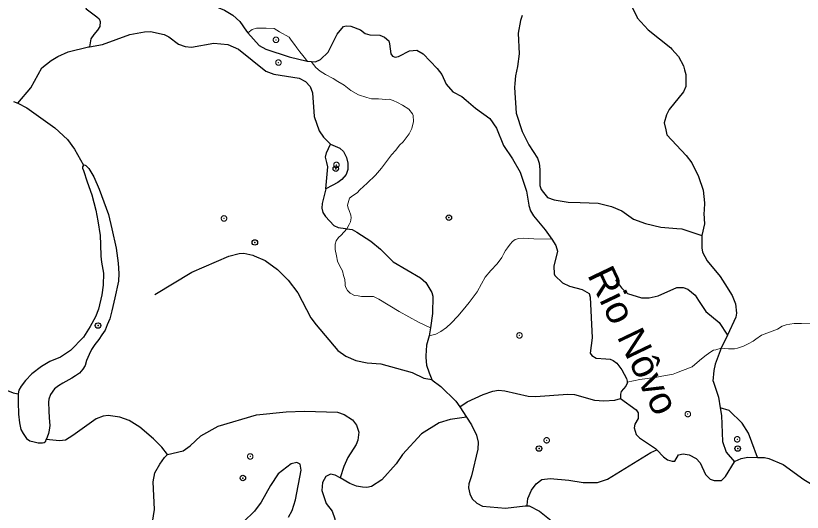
# Model space of a CAD drawing. Extents: x 267.7 to 296, y 7537.7 to 7565.8.
# Drawn here: x 270.298 to 273.164, y 7556.895 to 7558.704 of the extents above; entities that cross this region are included whole.
import ezdxf
from ezdxf.enums import TextEntityAlignment as Align

# ---------------------------------------------------------------- set-up
doc = ezdxf.new("R2010")
doc.units = 0
doc.header["$LTSCALE"] = 0.04
doc.header["$PDMODE"] = 32
doc.header["$PDSIZE"] = 0.02
doc.linetypes.add('SHORT_DASHED', pattern=[2.7, 1.5, -1.2])
for name, color, linetype, lineweight in [('2', 7, 'Continuous', 25), ('21', 7, 'SHORT_DASHED', 13), ('7', 7, 'Continuous', 25)]:
    doc.layers.add(name, color=color, linetype=linetype, lineweight=lineweight)
doc.layers.add('54', color=7, linetype='Continuous')
doc.layers.add('61', color=7, linetype='Continuous')

msp = doc.modelspace()

# ---------------------------------------------------------------- linework, layer by layer
at = {"layer": '2'}
for points in [[(270.5446, 7558.1593), (270.5418, 7558.1539), (270.5411, 7558.1483), (270.5446, 7558.1405), (270.5587, 7558.0989), (270.5756, 7558.0517), (270.5904, 7557.9961), (270.5974, 7557.9566), (270.6059, 7557.9031), (270.6066, 7557.8699), (270.608, 7557.8277), (270.6108, 7557.8058), (270.6179, 7557.7657), (270.6172, 7557.7227), (270.6122, 7557.6867), (270.5995, 7557.6346), (270.589, 7557.6071), (270.5692, 7557.5719), (270.5453, 7557.5331), (270.4974, 7557.4838), (270.4614, 7557.4605), (270.4227, 7557.4443), (270.3924, 7557.426), (270.3572, 7557.3999), (270.3332, 7557.3746), (270.3184, 7557.3541), (270.3099, 7557.3401), (270.3064, 7557.326)], [(270.5446, 7558.1593), (270.5486, 7558.1601), (270.5535, 7558.1587), (270.5645, 7558.1467), (270.5824, 7558.1164), (270.6022, 7558.0717), (270.6365, 7557.9803), (270.648, 7557.9276), (270.6639, 7557.857), (270.6708, 7557.8024), (270.6738, 7557.7651), (270.6723, 7557.7368), (270.6594, 7557.6762), (270.648, 7557.6285), (270.641, 7557.5997), (270.6311, 7557.5773), (270.6241, 7557.5589), (270.6117, 7557.541), (270.6003, 7557.5246), (270.5858, 7557.5067), (270.5744, 7557.4874), (270.5655, 7557.4695), (270.5565, 7557.4481), (270.5511, 7557.4297), (270.5431, 7557.4168), (270.5302, 7557.4019), (270.5163, 7557.3915), (270.5019, 7557.3835), (270.4701, 7557.3651), (270.4537, 7557.3552), (270.4398, 7557.3443), (270.4248, 7557.3244), (270.4189, 7557.307), (270.4179, 7557.2956), (270.4184, 7557.2647), (270.4199, 7557.2394), (270.4219, 7557.2116), (270.4199, 7557.1937), (270.4169, 7557.1823), (270.4129, 7557.1684), (270.4092, 7557.1604)], [(270.3064, 7557.326), (270.3064, 7557.2964), (270.3078, 7557.2527), (270.3114, 7557.221), (270.317, 7557.1963), (270.3247, 7557.1815), (270.3367, 7557.1639), (270.3494, 7557.1554), (270.3649, 7557.1512), (270.3797, 7557.1477), (270.3959, 7557.1477), (270.4022, 7557.1498), (270.4072, 7557.154), (270.4092, 7557.1604)]]:
    msp.add_lwpolyline(points, dxfattribs=at)
msp.add_point((270.598, 7557.5751), dxfattribs=at)
at = {"layer": '21'}
for points in [[(271.1436, 7558.6417), (271.1597, 7558.6537), (271.1749, 7558.6582), (271.2105, 7558.659), (271.2393, 7558.6567), (271.2597, 7558.6446), (271.2945, 7558.6257), (271.3021, 7558.6151), (271.3135, 7558.5984), (271.3218, 7558.587), (271.3331, 7558.5719), (271.3445, 7558.559), (271.3543, 7558.5469), (271.3596, 7558.5385)], [(271.3749, 7558.5371), (271.3914, 7558.5151), (271.4073, 7558.5022), (271.427, 7558.4894), (271.4551, 7558.4757), (271.4717, 7558.4644), (271.4944, 7558.4507), (271.5194, 7558.4311), (271.5467, 7558.4152), (271.5777, 7558.4061), (271.5951, 7558.4015), (271.6194, 7558.4008), (271.6466, 7558.3985), (271.6587, 7558.3993), (271.6731, 7558.3947), (271.6898, 7558.3879), (271.7072, 7558.3781), (271.7307, 7558.3629), (271.7443, 7558.347), (271.7466, 7558.3402), (271.7473, 7558.319), (271.742, 7558.2925), (271.7322, 7558.2736), (271.7095, 7558.244), (271.6966, 7558.2319), (271.6837, 7558.2145), (271.6671, 7558.1971), (271.6527, 7558.1774), (271.6315, 7558.1486), (271.6088, 7558.1236), (271.5785, 7558.0934), (271.552, 7558.0691), (271.5421, 7558.0585), (271.5255, 7558.0479), (271.5141, 7558.0388), (271.5073, 7558.0139), (271.5096, 7558.0033), (271.5126, 7557.9942), (271.5194, 7557.9775), (271.5202, 7557.9677), (271.5179, 7557.9533), (271.5134, 7557.9427), (271.5042, 7557.928)], [(271.5042, 7557.928), (271.4838, 7557.9048), (271.474, 7557.8957), (271.4657, 7557.8836), (271.4626, 7557.8715), (271.4626, 7557.8518), (271.4672, 7557.8291), (271.471, 7557.8102), (271.4793, 7557.7912), (271.4884, 7557.7746), (271.4929, 7557.7579), (271.4975, 7557.7428), (271.499, 7557.7276), (271.499, 7557.7216), (271.5005, 7557.7133), (271.5065, 7557.7026), (271.5171, 7557.6936), (271.533, 7557.6852), (271.5459, 7557.683), (271.558, 7557.6814), (271.5785, 7557.6814), (271.5906, 7557.6814), (271.6012, 7557.6807), (271.6209, 7557.6716), (271.6951, 7557.6269), (271.7663, 7557.5876), (271.809, 7557.5667)], [(271.8045, 7557.5381), (271.8291, 7557.5444), (271.8473, 7557.5535), (271.8677, 7557.5686), (271.8851, 7557.5845), (271.9094, 7557.6088), (271.9283, 7557.6322), (271.9502, 7557.6595), (271.979, 7557.6981), (271.9957, 7557.7276), (272.0093, 7557.7511), (272.0298, 7557.7761), (272.0525, 7557.8003), (272.0691, 7557.823), (272.0767, 7557.8382), (272.0828, 7557.8488), (272.0896, 7557.8586), (272.0994, 7557.8715), (272.1085, 7557.8813), (272.1183, 7557.8889), (272.1312, 7557.8927), (272.1501, 7557.8935), (272.1865, 7557.8912), (272.2513, 7557.8895)], [(272.8686, 7557.4924), (272.895, 7557.4901), (272.917, 7557.4901), (272.9277, 7557.4929), (272.9502, 7557.5002), (272.9677, 7557.5087), (272.9858, 7557.5189), (272.9948, 7557.5262), (273.0157, 7557.5397), (273.0444, 7557.551), (273.0738, 7557.5617), (273.0913, 7557.573), (273.1059, 7557.5781), (273.1195, 7557.5803), (273.1347, 7557.5826), (273.1612, 7557.5826), (273.1939, 7557.5837)], [(272.5261, 7557.3688), (272.5718, 7557.379), (272.6338, 7557.3869), (272.6519, 7557.3914), (272.6936, 7557.3987), (272.706, 7557.4032), (272.728, 7557.4111), (272.763, 7557.4252), (272.79, 7557.4478), (272.8092, 7557.4636), (272.8278, 7557.4771), (272.8402, 7557.485), (272.8493, 7557.4867), (272.8686, 7557.4924)]]:
    msp.add_lwpolyline(points, dxfattribs=at)
for p in [(271.2463, 7558.6159), (271.2554, 7558.5332), (271.4667, 7558.1603), (271.057, 7557.9655), (272.1336, 7557.5393), (272.7472, 7557.2527), (272.2328, 7557.1572), (272.9272, 7557.1609), (271.1526, 7557.0984)]:
    msp.add_point(p, dxfattribs=at)
at = {"layer": '54'}
for p in [(271.4643, 7558.1465), (271.8765, 7557.9684), (271.1694, 7557.8779), (272.205, 7557.1272), (272.9289, 7557.1272), (271.1258, 7557.0199)]:
    msp.add_point(p, dxfattribs=at)
at = {"layer": '7'}
for p, q in [((270.2902, 7558.3919), (270.3059, 7558.3849)), ((272.8912, 7557.5397), (272.8686, 7557.4924)), ((271.916, 7557.2788), (271.9408, 7557.2409))]:
    msp.add_line(p, q, dxfattribs=at)
for points in [[(270.7124, 7558.7626), (270.7121, 7558.7621), (270.6936, 7558.7622), (270.6228, 7558.7724), (270.5976, 7558.7709), (270.5785, 7558.7623), (270.561, 7558.751), (270.5528, 7558.7367), (270.5547, 7558.7287), (270.594, 7558.6998), (270.6021, 7558.6925), (270.6062, 7558.6832), (270.6051, 7558.6647), (270.5959, 7558.6514), (270.5826, 7558.635), (270.5723, 7558.6196), (270.5666, 7558.591)], [(270.9731, 7558.7578), (270.9969, 7558.7495), (271.0592, 7558.7238), (271.0887, 7558.7053), (271.1145, 7558.6832), (271.1386, 7558.6474), (271.1436, 7558.6417)], [(272.543, 7558.7366), (272.5623, 7558.698), (272.563, 7558.6967), (272.6032, 7558.6519), (272.6849, 7558.5868), (272.6887, 7558.5825), (272.7127, 7558.5549), (272.7309, 7558.5216), (272.735, 7558.5064), (272.7397, 7558.4891), (272.7403, 7558.4463), (272.7313, 7558.427), (272.6797, 7558.3617), (272.67, 7558.343), (272.661, 7558.3137), (272.6666, 7558.2885), (272.6707, 7558.2697), (272.7412, 7558.1952), (272.7618, 7558.1676), (272.786, 7558.1182), (272.8027, 7558.0684), (272.8083, 7558.0228), (272.8066, 7557.995), (272.8059, 7557.9833), (272.8083, 7557.9453), (272.7979, 7557.9033)], [(272.143, 7558.7051), (272.137, 7558.6865), (272.1293, 7558.6404), (272.1324, 7558.5644), (272.1267, 7558.5193), (272.1187, 7558.4853), (272.1167, 7558.4573), (272.1156, 7558.4426), (272.1213, 7558.3494), (272.1435, 7558.2825), (272.1679, 7558.2338), (272.1994, 7558.1849), (272.2056, 7558.1664), (272.2083, 7558.1442), (272.2079, 7558.0858), (272.2127, 7558.0707), (272.2214, 7558.0598), (272.2358, 7558.0418), (272.2602, 7558.033), (272.3106, 7558.0249), (272.3544, 7558.0232), (272.421, 7558.0206), (272.4688, 7558.0094), (272.5071, 7557.9936), (272.5491, 7557.9629), (272.5925, 7557.9469), (272.6491, 7557.9333), (272.7074, 7557.9285), (272.7249, 7557.9271), (272.7979, 7557.9033)], [(271.3749, 7558.5371), (271.3903, 7558.5358), (271.4092, 7558.5446), (271.4363, 7558.5713), (271.4699, 7558.6362), (271.4922, 7558.6641), (271.5021, 7558.6668), (271.5193, 7558.666), (271.5544, 7558.6519), (271.5719, 7558.6392), (271.5883, 7558.6338), (271.6246, 7558.6333), (271.6422, 7558.6262), (271.6578, 7558.6118), (271.6603, 7558.6011), (271.6651, 7558.5646), (271.6716, 7558.557), (271.6808, 7558.5529), (271.6931, 7558.5549), (271.6954, 7558.5562), (271.7331, 7558.5765), (271.76, 7558.5781), (271.7822, 7558.5644), (271.8335, 7558.5117), (271.8509, 7558.4894), (271.867, 7558.4543), (271.8904, 7558.427), (271.9233, 7558.4099), (271.9399, 7558.3956), (271.973, 7558.3671), (272.0258, 7558.329), (272.0502, 7558.2937), (272.0756, 7558.2316), (272.1086, 7558.183), (272.1366, 7558.1335), (272.1593, 7558.0645), (272.1677, 7558.0143), (272.168, 7558.0124), (272.1741, 7557.9931), (272.1845, 7557.9746), (272.2279, 7557.9242), (272.2513, 7557.8895)], [(270.5666, 7558.591), (270.6145, 7558.5988), (270.7136, 7558.6355), (270.7671, 7558.6451), (270.7895, 7558.6458), (270.8386, 7558.6349), (270.8557, 7558.6264), (270.8915, 7558.5996), (270.9151, 7558.5919), (270.9388, 7558.5892), (271.0197, 7558.604), (271.0708, 7558.5989), (271.1095, 7558.5824), (271.2096, 7558.5021), (271.2384, 7558.4903), (271.3308, 7558.4768), (271.3536, 7558.4644), (271.3708, 7558.4465), (271.3793, 7558.4233), (271.386, 7558.3369), (271.4036, 7558.2848), (271.4201, 7558.2614), (271.4445, 7558.2364)], [(271.1436, 7558.6417), (271.1847, 7558.5949), (271.2095, 7558.5815), (271.2939, 7558.5539), (271.3596, 7558.5385)], [(270.3059, 7558.3849), (270.3532, 7558.4408), (270.3928, 7558.5137), (270.4269, 7558.5403), (270.452, 7558.5554), (270.489, 7558.572), (270.5634, 7558.5905), (270.5666, 7558.591)], [(271.3596, 7558.5385), (271.3629, 7558.5382), (271.3749, 7558.5371)], [(270.3059, 7558.3849), (270.3062, 7558.3848), (270.3391, 7558.3688), (270.4406, 7558.295), (270.4862, 7558.2528), (270.5118, 7558.2176), (270.5446, 7558.1593)], [(271.4279, 7558.0729), (271.4348, 7558.1529), (271.4313, 7558.1689), (271.427, 7558.1885), (271.4303, 7558.2046), (271.4445, 7558.2364)], [(271.4445, 7558.2364), (271.4446, 7558.2363), (271.479, 7558.2213), (271.4796, 7558.2208), (271.493, 7558.209), (271.5033, 7558.1875), (271.5084, 7558.1669), (271.5084, 7558.1433), (271.5022, 7558.1249), (271.4868, 7558.1074), (271.4714, 7558.0961), (271.4509, 7558.0848), (271.4279, 7558.0729)], [(271.4279, 7558.0729), (271.4143, 7558.0202), (271.4131, 7558.0025), (271.4177, 7557.9872), (271.4263, 7557.9729), (271.4571, 7557.9401), (271.4725, 7557.9329), (271.4992, 7557.9288), (271.5042, 7557.928)], [(271.5042, 7557.928), (271.5238, 7557.9247), (271.5412, 7557.9155), (271.5921, 7557.8821), (271.6279, 7557.8532), (271.6735, 7557.8078), (271.7728, 7557.749), (271.7923, 7557.7319), (271.8147, 7557.696), (271.818, 7557.6822), (271.8173, 7557.6187), (271.809, 7557.5667), (271.8045, 7557.5381)], [(272.2513, 7557.8895), (272.2667, 7557.8665), (272.2719, 7557.8459), (272.2593, 7557.7913), (272.2596, 7557.764), (272.2625, 7557.7577), (272.2902, 7557.7309), (272.3156, 7557.7182), (272.3624, 7557.7067), (272.3872, 7557.6917), (272.3917, 7557.679), (272.3989, 7557.531), (272.3909, 7557.4743), (272.3968, 7557.4657), (272.4135, 7557.4568), (272.4487, 7557.454), (272.4647, 7557.4527), (272.4753, 7557.4478), (272.4885, 7557.4379), (272.5073, 7557.4134), (272.524, 7557.3825), (272.5261, 7557.3728), (272.5261, 7557.3688)], [(272.7979, 7557.9033), (272.798, 7557.8583), (272.8012, 7557.843), (272.818, 7557.8109), (272.8653, 7557.7538), (272.8818, 7557.7274), (272.9082, 7557.6851), (272.9207, 7557.6544), (272.9247, 7557.62), (272.9224, 7557.6052), (272.8912, 7557.5397)], [(270.8046, 7557.6883), (270.9398, 7557.7698), (271.0748, 7557.8275), (271.1128, 7557.8381), (271.1293, 7557.8384), (271.1615, 7557.8313), (271.1665, 7557.8291), (271.2066, 7557.8118), (271.2518, 7557.779), (271.2914, 7557.7407), (271.3262, 7557.6946), (271.3735, 7557.6039), (271.3925, 7557.5776), (271.4718, 7557.4847), (271.5011, 7557.4636), (271.5376, 7557.4482), (271.5786, 7557.4396), (271.6282, 7557.4353), (271.7427, 7557.4039), (271.7851, 7557.3838), (271.7925, 7557.3823), (271.8139, 7557.3781)], [(272.484, 7557.7423), (272.506, 7557.7126), (272.5272, 7557.6915), (272.5781, 7557.6766), (272.6064, 7557.6766), (272.6396, 7557.6837), (272.7073, 7557.7142), (272.7301, 7557.7143), (272.7468, 7557.7077), (272.7745, 7557.6863), (272.7867, 7557.667), (272.8126, 7557.6262), (272.8612, 7557.5861), (272.8912, 7557.5397)], [(271.8045, 7557.5381), (271.795, 7557.5037), (271.7924, 7557.4651), (271.792, 7557.4586), (271.7952, 7557.4304), (271.8049, 7557.4033), (271.8139, 7557.3781)], [(272.8686, 7557.4924), (272.8472, 7557.4347), (272.8418, 7557.4118), (272.8389, 7557.373), (272.8391, 7557.3725), (272.8591, 7557.3139), (272.8656, 7557.276)], [(271.8139, 7557.3781), (271.814, 7557.3779), (271.8476, 7557.3533), (271.902, 7557.3002), (271.916, 7557.2788)], [(272.5261, 7557.3688), (272.5261, 7557.3649), (272.5217, 7557.3546), (272.5046, 7557.335), (272.5013, 7557.3258), (272.5017, 7557.3097), (272.5023, 7557.3093)], [(269.9297, 7557.2438), (269.9349, 7557.2729), (269.9482, 7557.3017), (269.9595, 7557.3143), (269.9813, 7557.3317), (270.0585, 7557.3505), (270.1206, 7557.3613), (270.1825, 7557.3649), (270.2038, 7557.3622), (270.2476, 7557.347), (270.2888, 7557.3302), (270.3064, 7557.326)], [(271.916, 7557.2788), (271.9431, 7557.297), (272.0018, 7557.3242), (272.0361, 7557.336), (272.0571, 7557.3398), (272.0804, 7557.3379), (272.165, 7557.3175), (272.1925, 7557.3165), (272.3099, 7557.3249), (272.3338, 7557.324), (272.4074, 7557.3035), (272.4416, 7557.3005), (272.4815, 7557.304), (272.5023, 7557.3093)], [(272.5023, 7557.3093), (272.5591, 7557.2682), (272.5659, 7557.2575), (272.5665, 7557.237), (272.5536, 7557.216), (272.5516, 7557.2029), (272.5586, 7557.1787), (272.5707, 7557.1659), (272.63, 7557.1272), (272.6348, 7557.1221)], [(270.8517, 7557.1049), (270.9082, 7557.1188), (270.9332, 7557.1372), (270.9724, 7557.1737), (271.0358, 7557.2092), (271.1755, 7557.2506), (271.2831, 7557.2607), (271.3504, 7557.2633), (271.4705, 7557.2593), (271.4951, 7557.2516), (271.5256, 7557.2322), (271.5397, 7557.2127), (271.548, 7557.1867), (271.5446, 7557.1582), (271.539, 7557.142), (271.5086, 7557.094), (271.4936, 7557.0613), (271.4807, 7557.0202)], [(273.0017, 7557.0948), (272.9804, 7557.1507), (272.968, 7557.1834), (272.9451, 7557.2201), (272.8975, 7557.266), (272.8656, 7557.276)], [(272.8656, 7557.276), (272.8705, 7557.2474), (272.8731, 7557.1534), (272.887, 7557.1139), (272.9175, 7557.0789)], [(270.8517, 7557.1049), (270.831, 7557.1323), (270.8006, 7557.1631), (270.7497, 7557.2056), (270.711, 7557.2293), (270.6772, 7557.2421), (270.6344, 7557.2478), (270.6165, 7557.2457), (270.5907, 7557.2354), (270.5065, 7557.1744), (270.4796, 7557.1582), (270.4573, 7557.1552), (270.4092, 7557.1604)], [(271.9408, 7557.2409), (271.8808, 7557.2327), (271.8414, 7557.2209), (271.7772, 7557.1805), (271.7073, 7557.105), (271.6839, 7557.0715), (271.6319, 7557.0132), (271.5948, 7556.9884), (271.5769, 7556.9847), (271.5617, 7556.9871), (271.5393, 7556.9906), (271.5153, 7557.0003), (271.4807, 7557.0202)], [(271.9408, 7557.2409), (271.9589, 7557.2133), (271.9769, 7557.1755), (271.9831, 7557.1505), (271.9824, 7557.1252), (271.9594, 7557.0273), (271.9495, 7556.9989), (271.9484, 7556.9842), (271.9531, 7556.9626), (271.9612, 7556.944), (271.9784, 7556.9282), (271.999, 7556.9169), (272.0828, 7556.9096), (272.154, 7556.9187), (272.1619, 7556.9184)], [(272.1619, 7556.9184), (272.1621, 7556.9205), (272.1642, 7556.9458), (272.1781, 7556.9755), (272.1941, 7556.999), (272.2155, 7557.0146), (272.246, 7557.018), (272.314, 7557.0121), (272.3655, 7557.0034), (272.4175, 7557.0035), (272.4543, 7557.0151), (272.6122, 7557.1126), (272.6348, 7557.1221)], [(272.6348, 7557.1221), (272.6582, 7557.0968), (272.6737, 7557.0861), (272.6901, 7557.0809), (272.6999, 7557.0817), (272.7138, 7557.1043), (272.7304, 7557.1085), (272.7515, 7557.1038), (272.7772, 7557.0906), (272.7926, 7557.0756), (272.8113, 7557.0332), (272.8286, 7557.0157), (272.8435, 7557.0102), (272.8702, 7557.011), (272.885, 7557.0252), (272.9175, 7557.0789)], [(270.787, 7556.7966), (270.8041, 7556.9056), (270.7985, 7557.0065), (270.8049, 7557.0383), (270.8235, 7557.0706), (270.8402, 7557.0943), (270.8517, 7557.1049)], [(272.9175, 7557.0789), (272.9193, 7557.0818), (272.9415, 7557.0909), (272.9664, 7557.0953), (273.0017, 7557.0948)], [(273.0017, 7557.0948), (273.0264, 7557.0945), (273.0429, 7557.0913), (273.0948, 7557.0693), (273.1699, 7557.0147), (273.2406, 7556.9724), (273.2675, 7556.961), (273.2829, 7556.9544), (273.3466, 7556.943), (273.3708, 7556.9483)], [(271.2924, 7556.8774), (271.3057, 7556.9013), (271.3177, 7556.9404), (271.3382, 7557.048), (271.3343, 7557.0707), (271.3227, 7557.0762), (271.3014, 7557.0714), (271.2549, 7557.0352), (271.2262, 7556.9926), (271.1928, 7556.9321), (271.1684, 7556.8987), (271.1285, 7556.86)], [(271.4807, 7557.0202), (271.4627, 7557.0306), (271.4453, 7557.0337), (271.4285, 7557.0251), (271.4158, 7557.0034), (271.4141, 7556.974), (271.4291, 7556.9274), (271.4509, 7556.899), (271.4604, 7556.8709), (271.4623, 7556.8482), (271.4572, 7556.8262), (271.4494, 7556.8098), (271.4237, 7556.7835), (271.4115, 7556.7787), (271.3705, 7556.7763), (271.3322, 7556.7797), (271.3311, 7556.7807)], [(272.1619, 7556.9184), (272.1693, 7556.9181), (272.2066, 7556.8986), (272.2426, 7556.8703), (272.2692, 7556.8418), (272.2941, 7556.8091), (272.3017, 7556.7794), (272.303, 7556.7532)]]:
    msp.add_lwpolyline(points, dxfattribs=at)

# ---------------------------------------------------------------- texts
at = {"layer": '61', "width": 1.05}
msp.add_text('Rio Nôvo', height=0.1, rotation=295.561, dxfattribs=at).set_placement((272.5042, 7557.4999), align=Align.CENTER)

doc.saveas('drawing.dxf')
